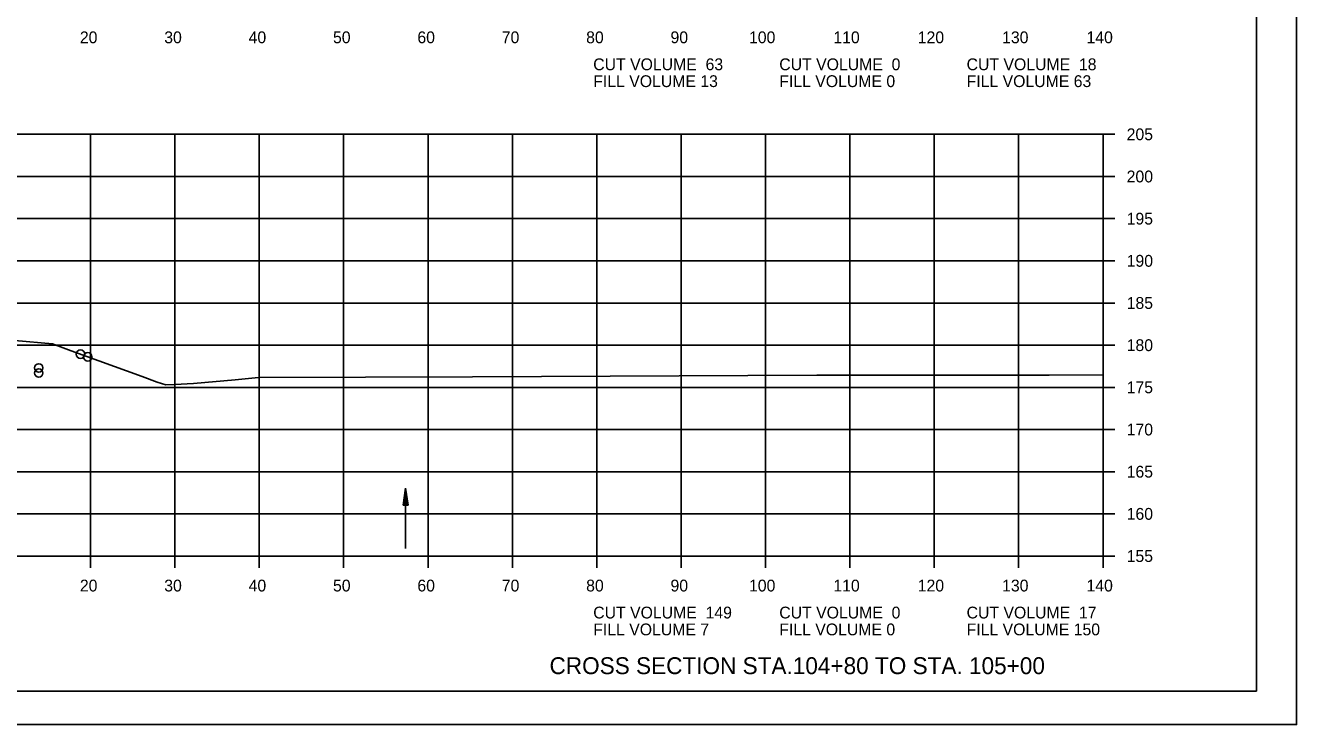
# Model space of a CAD drawing. Extents: x 1372132 to 1372465, y 380083 to 381790.
# Drawn here: x 1372314.3 to 1372464.9, y 380296.8 to 380379.7 of the extents above; entities that cross this region are included whole.
import ezdxf

# ---------------------------------------------------------------- set-up
doc = ezdxf.new("R2010")
doc.units = 0
for name, color, linetype in [('R_Axis', 7, 'Continuous'), ('R_Axis Annot', 7, 'Continuous'), ('R_Border', 7, 'Continuous'), ('R_Dimension', 7, 'Continuous'), ('R_Draft', 7, 'Continuous'), ('R_Exist Surface', 7, 'Continuous'), ('R_Grid', 7, 'Continuous'), ('R_No Plot', 7, 'Continuous')]:
    doc.layers.add(name, color=color, linetype=linetype)

msp = doc.modelspace()

# ---------------------------------------------------------------- linework, layer by layer
at = {"layer": 'R_Axis'}
for p, q in [((1372442.01, 380316.81), (1372442.01, 380366.81)), ((1372443.41, 380366.81), (1372442.01, 380366.81)), ((1372443.41, 380361.81), (1372442.01, 380361.81)), ((1372443.41, 380356.81), (1372442.01, 380356.81)), ((1372443.41, 380351.81), (1372442.01, 380351.81)), ((1372443.41, 380346.81), (1372442.01, 380346.81)), ((1372443.41, 380341.81), (1372442.01, 380341.81)), ((1372443.41, 380336.81), (1372442.01, 380336.81)), ((1372443.41, 380331.81), (1372442.01, 380331.81)), ((1372443.41, 380326.81), (1372442.01, 380326.81)), ((1372443.41, 380321.81), (1372442.01, 380321.81)), ((1372162.01, 380316.81), (1372442.01, 380316.81)), ((1372322.01, 380315.41), (1372322.01, 380316.81)), ((1372332.01, 380315.41), (1372332.01, 380316.81)), ((1372342.01, 380315.41), (1372342.01, 380316.81)), ((1372352.01, 380315.41), (1372352.01, 380316.81)), ((1372362.01, 380315.41), (1372362.01, 380316.81)), ((1372372.01, 380315.41), (1372372.01, 380316.81)), ((1372382.01, 380315.41), (1372382.01, 380316.81)), ((1372392.01, 380315.41), (1372392.01, 380316.81)), ((1372402.01, 380315.41), (1372402.01, 380316.81)), ((1372412.01, 380315.41), (1372412.01, 380316.81)), ((1372422.01, 380315.41), (1372422.01, 380316.81)), ((1372432.01, 380315.41), (1372432.01, 380316.81)), ((1372442.01, 380315.41), (1372442.01, 380316.81)), ((1372443.41, 380316.81), (1372442.01, 380316.81))]:
    msp.add_line(p, q, dxfattribs=at)
at = {"layer": 'R_Border'}
for q in [(1372460.19, 380506.27), (1372144.01, 380300.81)]:
    msp.add_line((1372460.19, 380300.81), q, dxfattribs=at)
at = {"layer": 'R_Dimension'}
for p, q in [((1372359.05, 380322.86), (1372359.35, 380324.86)), ((1372359.05, 380322.86), (1372359.35, 380324.86)), ((1372359.1, 380322.86), (1372359.35, 380324.53)), ((1372359.1, 380322.86), (1372359.35, 380324.53)), ((1372359.15, 380322.86), (1372359.35, 380324.18)), ((1372359.15, 380322.86), (1372359.35, 380324.18)), ((1372359.65, 380322.86), (1372359.35, 380324.86)), ((1372359.65, 380322.86), (1372359.35, 380324.86)), ((1372359.6, 380322.86), (1372359.35, 380324.53)), ((1372359.6, 380322.86), (1372359.35, 380324.53)), ((1372359.55, 380322.86), (1372359.35, 380324.18)), ((1372359.55, 380322.86), (1372359.35, 380324.18)), ((1372359.05, 380322.86), (1372359.65, 380322.86)), ((1372359.05, 380322.86), (1372359.65, 380322.86)), ((1372359.2, 380322.86), (1372359.35, 380323.85)), ((1372359.2, 380322.86), (1372359.35, 380323.85)), ((1372359.25, 380322.86), (1372359.35, 380323.51)), ((1372359.25, 380322.86), (1372359.35, 380323.51)), ((1372359.3, 380322.86), (1372359.35, 380323.18)), ((1372359.3, 380322.86), (1372359.35, 380323.18)), ((1372359.5, 380322.86), (1372359.35, 380323.85)), ((1372359.5, 380322.86), (1372359.35, 380323.85)), ((1372359.45, 380322.86), (1372359.35, 380323.51)), ((1372359.45, 380322.86), (1372359.35, 380323.51)), ((1372359.39, 380322.86), (1372359.35, 380323.18)), ((1372359.39, 380322.86), (1372359.35, 380323.18))]:
    msp.add_line(p, q, dxfattribs=at)
at = {"layer": 'R_Draft'}
msp.add_line((1372359.35, 380317.72), (1372359.35, 380324.86), dxfattribs=at)
at = {"layer": 'R_Exist Surface'}
msp.add_lwpolyline([(1372313.04, 380342.36), (1372317.49, 380341.96), (1372319.71, 380341.14), (1372328.13, 380338.1), (1372329.91, 380337.42), (1372330.92, 380337.1), (1372332.01, 380337.15), (1372334.22, 380337.25), (1372339.16, 380337.72), (1372341.92, 380337.99), (1372367.27, 380338.06), (1372408.09, 380338.24), (1372435.64, 380338.27), (1372442.01, 380338.28)], dxfattribs=at)
at = {"layer": 'R_Grid'}
for p, q in [((1372162.01, 380366.81), (1372442.01, 380366.81)), ((1372322.01, 380316.81), (1372322.01, 380366.81)), ((1372332.01, 380316.81), (1372332.01, 380366.81)), ((1372342.01, 380316.81), (1372342.01, 380366.81)), ((1372352.01, 380316.81), (1372352.01, 380366.81)), ((1372362.01, 380316.81), (1372362.01, 380366.81)), ((1372372.01, 380316.81), (1372372.01, 380366.81)), ((1372382.01, 380316.81), (1372382.01, 380366.81)), ((1372392.01, 380316.81), (1372392.01, 380366.81)), ((1372402.01, 380316.81), (1372402.01, 380366.81)), ((1372412.01, 380316.81), (1372412.01, 380366.81)), ((1372422.01, 380316.81), (1372422.01, 380366.81)), ((1372432.01, 380316.81), (1372432.01, 380366.81)), ((1372442.01, 380316.81), (1372442.01, 380366.81)), ((1372162.01, 380361.81), (1372442.01, 380361.81)), ((1372162.01, 380356.81), (1372442.01, 380356.81)), ((1372162.01, 380351.81), (1372442.01, 380351.81)), ((1372162.01, 380346.81), (1372442.01, 380346.81)), ((1372162.01, 380341.81), (1372442.01, 380341.81)), ((1372162.01, 380336.81), (1372442.01, 380336.81)), ((1372162.01, 380331.81), (1372442.01, 380331.81)), ((1372162.01, 380326.81), (1372442.01, 380326.81)), ((1372162.01, 380321.81), (1372442.01, 380321.81)), ((1372162.01, 380316.81), (1372442.01, 380316.81))]:
    msp.add_line(p, q, dxfattribs=at)
at = {"layer": 'R_No Plot'}
msp.add_line((1372131.61, 380296.83), (1372464.95, 380296.83), dxfattribs=at)
for points in [[(1372131.61, 380510.17), (1372464.95, 380510.17), (1372464.95, 380296.83), (1372131.61, 380296.83)], [(1372377.93, 380506.27), (1372377.93, 380496.39), (1372413.67, 380496.39), (1372413.67, 380493.47), (1372436.87, 380493.47), (1372436.87, 380469.14), (1372460.19, 380469.14), (1372460.19, 380300.81), (1372144.01, 380300.81), (1372144.01, 380506.27)]]:
    msp.add_lwpolyline(points, close=True, dxfattribs=at)
for centre in [(1372320.82, 380340.74), (1372321.68, 380340.43), (1372315.87, 380339.11), (1372315.87, 380338.51)]:
    msp.add_circle(centre, 0.5, dxfattribs=at)

# ---------------------------------------------------------------- texts
at = {"layer": 'R_Axis Annot'}
for s, p in [('20', (1372320.75, 380377.61)), ('30', (1372330.75, 380377.61)), ('40', (1372340.75, 380377.61)), ('50', (1372350.75, 380377.61)), ('60', (1372360.75, 380377.61)), ('70', (1372370.75, 380377.61)), ('80', (1372380.75, 380377.61)), ('90', (1372390.75, 380377.61)), ('100', (1372400.05, 380377.61)), ('110', (1372410.05, 380377.61)), ('120', (1372420.05, 380377.61)), ('130', (1372430.05, 380377.61)), ('140', (1372440.05, 380377.61)), ('CUT VOLUME  63', (1372381.59, 380374.41)), ('CUT VOLUME  0', (1372403.64, 380374.41)), ('CUT VOLUME  18', (1372425.84, 380374.41)), ('FILL VOLUME 13', (1372381.59, 380372.41)), ('FILL VOLUME 0', (1372403.64, 380372.41)), ('FILL VOLUME 63', (1372425.84, 380372.41)), ('205', (1372444.81, 380366.11)), ('200', (1372444.81, 380361.11)), ('195', (1372444.81, 380356.11)), ('190', (1372444.81, 380351.11)), ('185', (1372444.81, 380346.11)), ('180', (1372444.81, 380341.11)), ('175', (1372444.81, 380336.11)), ('170', (1372444.81, 380331.11)), ('165', (1372444.81, 380326.11)), ('160', (1372444.81, 380321.11)), ('155', (1372444.81, 380316.11)), ('20', (1372320.75, 380312.61)), ('30', (1372330.75, 380312.61)), ('40', (1372340.75, 380312.61)), ('50', (1372350.75, 380312.61)), ('60', (1372360.75, 380312.61)), ('70', (1372370.75, 380312.61)), ('80', (1372380.75, 380312.61)), ('90', (1372390.75, 380312.61)), ('100', (1372400.05, 380312.61)), ('110', (1372410.05, 380312.61)), ('120', (1372420.05, 380312.61)), ('130', (1372430.05, 380312.61)), ('140', (1372440.05, 380312.61)), ('CUT VOLUME  149', (1372381.59, 380309.41)), ('CUT VOLUME  0', (1372403.64, 380309.41)), ('CUT VOLUME  17', (1372425.84, 380309.41)), ('FILL VOLUME 7', (1372381.59, 380307.41)), ('FILL VOLUME 0', (1372403.64, 380307.41)), ('FILL VOLUME 150', (1372425.84, 380307.41))]:
    msp.add_text(s, height=1.4, dxfattribs=at).set_placement(p)
at = {"layer": 'R_Draft'}
msp.add_text('CROSS SECTION STA.104+80 TO STA. 105+00', height=2, dxfattribs=at).set_placement((1372376.41, 380302.81))

doc.saveas('drawing.dxf')
